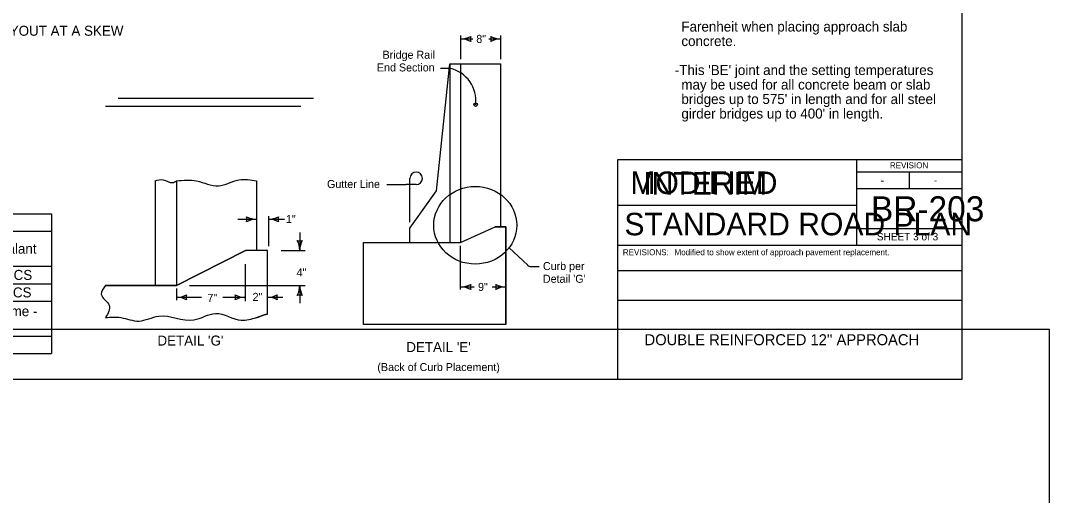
# Model space of a CAD drawing. Extents: x 10130 to 81668, y 5440 to 21644.
# Drawn here: x 18585 to 20643, y 7692 to 8642 of the extents above; entities that cross this region are included whole.
import ezdxf

# ---------------------------------------------------------------- set-up
doc = ezdxf.new("R2010")
doc.units = 0
for name, color, linetype in [('dsnCellElements', 7, 'Continuous'), ('dsnShtPlotShapeBatchPrint', 7, 'Continuous'), ('dsnstdblockInterim', 7, 'Continuous'), ('dsnStdBlockModified', 7, 'Continuous'), ('dsnStdBlockNotModified', 7, 'Continuous'), ('dsnStdBorder', 7, 'Continuous'), ('dsnStdLabel', 7, 'Continuous'), ('Level 1', 7, 'Continuous'), ('Level 5', 7, 'Continuous'), ('SheetBorder', 7, 'Continuous')]:
    doc.layers.add(name, color=color, linetype=linetype)

msp = doc.modelspace()

# ---------------------------------------------------------------- linework, layer by layer
at = {"layer": 'dsnCellElements'}
for p, q in [((19376.3, 8313.6), (19356.3, 8313.6)), ((19363.8, 8306.1), (19363.8, 8326.1))]:
    msp.add_line(p, q, dxfattribs=at)
msp.add_circle((19495.2, 8473.6), 3.54, dxfattribs=at)
msp.add_arc((19376.3, 8326.1), 12.5, 270, 180, dxfattribs=at)
at = {"layer": 'dsnShtPlotShapeBatchPrint'}
msp.add_lwpolyline([(17298.7, 5439.6), (20642.7, 5439.6), (20642.7, 8023.6), (17298.7, 8023.6)], close=True, dxfattribs=at)
at = {"layer": 'dsnStdBlockNotModified'}
for centre, radius, start, end in [((19465.1, 8647.4), 42.5, 270, 298.0725), ((19465.1, 8562.4), 42.5, 61.9275, 90), ((19500.8, 8604.9), 16.4, 162.2666, 197.7334), ((19509.8, 8604.9), 16.4, 342.2666, 17.7333), ((19545.4, 8647.4), 42.5, 241.9275, 270), ((19545.4, 8562.4), 42.5, 90, 118.0725), ((19021.3, 8244.2), 16.4, 342.2666, 17.7333), ((19056.9, 8286.7), 42.5, 241.9275, 270), ((19056.9, 8201.7), 42.5, 90, 118.0725), ((19080.7, 8286.7), 42.5, 270, 298.0725), ((19080.7, 8201.7), 42.5, 61.9275, 90), ((19116.4, 8244.2), 16.4, 162.2666, 197.7334), ((19143.4, 8217.5), 16.4, 252.2666, 287.7333), ((19100.9, 8181.9), 42.5, 360, 28.0725), ((19185.9, 8181.9), 42.5, 151.9275, 180), ((19100.9, 8112), 42.5, 331.9275, 360), ((19185.9, 8112), 42.5, 180, 208.0725), ((19465.1, 8151.4), 42.5, 270, 298.0725), ((19465.1, 8066.4), 42.5, 61.9275, 90), ((19500.8, 8108.9), 16.4, 162.2666, 197.7334), ((19519.7, 8108.9), 16.4, 342.2666, 17.7333), ((19555.4, 8151.4), 42.5, 241.9275, 270), ((19555.4, 8066.4), 42.5, 90, 118.0725), ((18896.9, 8130.6), 42.5, 270, 298.0725), ((18896.9, 8045.6), 42.5, 61.9275, 90), ((18932.5, 8088.1), 16.4, 162.2666, 197.7334), ((18998.4, 8088.1), 16.4, 342.2666, 17.7333), ((19034, 8130.6), 42.5, 241.9275, 270), ((19034, 8045.6), 42.5, 90, 118.0725), ((19143.4, 8076.3), 16.4, 72.2666, 107.7334)]:
    msp.add_arc(centre, radius, start, end, dxfattribs=at)
at = {"layer": 'dsnStdBorder'}
for p, q in [((19465.1, 8604.9), (19489.8, 8604.9)), ((19465.4, 8564.3), (19465.4, 8611.6)), ((19521.7, 8604.9), (19545.4, 8604.9)), ((19545.4, 8564.3), (19545.4, 8611.6)), ((19417.1, 8301.2), (19443.8, 8555.2)), ((19444.1, 8546), (19424.6, 8546)), ((19443.8, 8555.2), (19545.1, 8555.2)), ((19443.8, 8555.2), (19443.8, 8197.6)), ((19465.1, 8555.2), (19465.1, 8197.6)), ((19545.1, 8555.2), (19545.1, 8229.2)), ((18780.2, 8486.5), (19171.1, 8486.5)), ((18754.9, 8470.5), (19145.8, 8470.5)), ((19492.9, 8474.8), (19495.2, 8473.6)), ((18854.2, 8321), (18854.2, 8111.9)), ((18896.9, 8321), (18896.9, 8111.9)), ((19056.9, 8321), (19056.9, 8181.9)), ((19317.4, 8313.6), (19356.3, 8313.6)), ((19363.8, 8238.2), (19363.8, 8306.1)), ((19363.8, 8226.5), (19417.1, 8301.2)), ((18311.9, 8255.4), (18647, 8255.4)), ((18647, 8255.4), (18647, 7975.4)), ((19545.1, 8260.8), (19545.1, 8229.2)), ((19019.2, 8244.2), (19056.9, 8244.2)), ((19056.9, 8238.3), (19056.9, 8181.9)), ((19080.7, 8250.7), (19080.7, 8190.7)), ((19080.7, 8244.2), (19113, 8244.2)), ((18311.9, 8220.4), (18647, 8220.4)), ((19143.4, 8217.6), (19143.4, 8181.9)), ((19363.8, 8197.6), (19363.8, 8226.5)), ((19465.1, 8197.6), (19534.2, 8229.2)), ((19555.4, 8229.2), (19534.2, 8229.2)), ((19534.2, 8229.2), (19555.4, 8229.2)), ((19555.4, 8033.4), (19555.4, 8229.2)), ((19555.4, 8229.2), (19555.4, 8033.4)), ((19465.1, 8103.7), (19465.1, 8191.1)), ((19078.9, 8181.9), (19034.6, 8181.9)), ((19078.9, 8054.6), (19078.9, 8181.9)), ((19106.3, 8181.9), (19154.2, 8181.9)), ((19562.1, 8187.2), (19599.2, 8152.3)), ((18311.9, 8150.4), (18647, 8150.4)), ((19034, 8154.5), (19034, 8080.6)), ((19606, 8149.5), (19621.9, 8149.5)), ((18311.9, 8115.4), (18647, 8115.4)), ((18779.1, 8111.9), (18754.7, 8111.9)), ((18895.7, 8111.9), (18754.7, 8111.9)), ((18755, 8111.9), (18800.9, 8111.9)), ((18800.9, 8111.9), (18779.1, 8111.9)), ((18896.8, 8111.9), (18800.9, 8111.9)), ((18800.9, 8111.9), (18896.8, 8111.9)), ((18896.9, 8111.9), (18895.7, 8111.9)), ((18922.7, 8112), (19154.2, 8112)), ((19143.4, 8112), (19143.4, 8076.3)), ((19465.1, 8108.9), (19492.2, 8108.9)), ((19528, 8108.9), (19555.4, 8108.9)), ((18896.8, 8105.6), (18896.8, 8082.6)), ((18896.9, 8088.1), (18947.1, 8088.1)), ((18989.2, 8088.1), (19034, 8088.1)), ((19078.9, 8088.1), (19109.3, 8088.1)), ((18311.9, 8080.4), (18647, 8080.4)), ((18311.9, 8010.4), (18647, 8010.4)), ((18311.9, 7975.4), (18647, 7975.4))]:
    msp.add_line(p, q, dxfattribs=at)
for points in [[(19465.1, 8197.6), (19534.2, 8229.2)], [(19555.4, 8033.4), (19271, 8033.4), (19271, 8197.6), (19417.1, 8197.5), (19465.1, 8197.6)], [(19555.4, 8033.4), (19271, 8033.4), (19271, 8197.6), (19417.1, 8197.5), (19465.1, 8197.6)], [(19034.6, 8181.9), (18896.9, 8111.9), (18896.8, 8111.9)], [(18896.8, 8111.9), (19034.6, 8181.9)], [(19078.9, 8181.9), (19056.9, 8181.9), (19034.6, 8181.9)], [(19078.9, 8054.6), (19078.9, 8054.6), (19078.9, 8181.9)]]:
    msp.add_lwpolyline(points, dxfattribs=at)
for centre, radius, start, end in [((19429, 8481.1), 66.7, 353.5756, 76.8823), ((19606, 8159.5), 10, 226.7172, 270), ((19078.9, 8128.4), 40.3, 270, 298.0725), ((19078.9, 8047.8), 40.3, 61.9275, 90), ((19112.7, 8088.1), 15.6, 162.2666, 197.7334)]:
    msp.add_arc(centre, radius, start, end, dxfattribs=at)
msp.add_ellipse((19494.4, 8232.2), major_axis=(83, 0), ratio=0.93542, dxfattribs=at)
for points in [[(18854.2, 8321), (18869.9, 8323.4), (18889, 8317.6), (18896.9, 8321)], [(18896.9, 8321), (18937, 8321), (18980.7, 8310.9), (19021.5, 8323.2), (19056.9, 8321)], [(18754.7, 8111.9), (18746.4, 8094.3), (18762.2, 8072.1), (18755, 8047.6)], [(18754.7, 8111.9), (18746.4, 8094.3), (18762.2, 8072.1), (18755, 8047.6)], [(18755, 8047.6), (18785.5, 8047.6), (18821.7, 8040.6), (18861.3, 8050.5), (18931.3, 8042.9), (18975.1, 8055.8), (19026.4, 8042.4), (19056.9, 8047.6)], [(18755, 8047.6), (18785.5, 8047.6), (18821.7, 8040.6), (18861.3, 8050.5), (18931.3, 8042.9), (18975.1, 8055.8), (19026.4, 8042.4), (19056.9, 8047.6)], [(19056.9, 8047.6), (19071, 8052.7), (19076.3, 8054.2)]]:
    msp.add_spline(points, degree=3, dxfattribs=at)
msp.add_open_spline([(19056.9, 8047.6), (19057.8, 8047.9), (19058.7, 8048.2), (19059.6, 8048.5), (19060.6, 8048.8), (19061.5, 8049.2), (19062.4, 8049.5), (19064.2, 8050.2), (19066.1, 8051), (19067.9, 8051.7), (19069.7, 8052.3), (19071.5, 8053), (19073.4, 8053.5), (19074.3, 8053.8), (19075.2, 8054), (19076.1, 8054.2), (19076.6, 8054.3), (19077, 8054.4), (19077.5, 8054.4), (19077.9, 8054.5), (19078.4, 8054.5), (19078.9, 8054.6)], degree=3, dxfattribs=at)
at = {"layer": 'dsnStdLabel'}
for p, q in [((20256.6, 8364), (20256.6, 8272.7)), ((20256.6, 8339.1), (20467.5, 8339.1)), ((20362.1, 8339.1), (20362.1, 8305.9)), ((20256.6, 8305.9), (20467.5, 8305.9)), ((19779.5, 8272.7), (20256.6, 8272.7)), ((20256.6, 8272.7), (20256.6, 8192.7)), ((20467.5, 8224.9), (20256.6, 8224.9)), ((19779.5, 8192.7), (20467.5, 8192.7)), ((19779.5, 8141.7), (20467.5, 8141.7)), ((19779.5, 8082.7), (20467.5, 8082.7))]:
    msp.add_line(p, q, dxfattribs=at)
msp.add_lwpolyline([(19779.5, 8364), (20467.5, 8364), (20467.5, 7924), (19779.5, 7924)], close=True, dxfattribs=at)
msp.add_lwpolyline([(19779.5, 8364), (20467.5, 8364), (20467.5, 7924), (19779.5, 7924)], close=True, dxfattribs=at)
at = {"layer": 'SheetBorder'}
msp.add_lwpolyline([(17332.5, 9944), (20467.5, 9944), (20467.5, 7924), (17332.5, 7924)], close=True, dxfattribs=at)

# ---------------------------------------------------------------- texts
at = {"layer": 'dsnstdblockInterim'}
msp.add_text('INTERIM', height=45, dxfattribs=at).set_placement((19830.5, 8293.7))
at = {"layer": 'dsnStdBlockModified'}
for s, height, p in [('Approved List of Sealant', 20, (18325.5, 8175.4)), ('Dow - Dowsil 902 RCS', 20, (18336.3, 8122.9)), ('Sika - Sikasil 728 RCS', 20, (18337.8, 8087.9)), ('Watson Bowman Acme - ', 20, (18324.3, 8050.4)), ('(Back of Curb Placement)', 16, (19298.6, 7940.6))]:
    msp.add_text(s, height=height, dxfattribs=at).set_placement(p)
at = {"layer": 'dsnStdBlockNotModified'}
for s, height, p in [('APPROACH PAVEMENTS LAYOUT AT A SKEW', 20, (18200.7, 8611.3)), ('REVISIONS:', 12, (19789.5, 8172.3))]:
    msp.add_text(s, height=height, dxfattribs=at).set_placement(p)
at = {"layer": 'dsnStdBorder'}
for s, height, p in [('8"', 16, (19496.4, 8597.1)), ('Bridge Rail ', 16, (19309, 8565.3)), ('End Section', 16, (19297.7, 8539.9)), ('Gutter Line', 16, (19197.9, 8306.7)), ('1"', 16, (19115.7, 8236.7)), ('Curb per', 16, (19629.7, 8142.6)), ('4"', 16, (19137, 8129.8)), ("Detail 'G'", 16, (19629.7, 8117.2)), ('9"', 16, (19499.9, 8100.9)), ('7"', 16, (18958.7, 8078.9)), ('2"', 16, (19049, 8081)), ("DETAIL 'G'", 20, (18858.8, 7991.6)), ("DETAIL 'E'", 20, (19356.4, 7978.6))]:
    msp.add_text(s, height=height, dxfattribs=at).set_placement(p)
at = {"layer": 'dsnStdLabel'}
for s, height, p in [('REVISION', 12, (20323.6, 8346.2)), ('-', 15, (20305.1, 8314.7)), ('-', 15, (20411.6, 8315.1)), ('BR-203', 50, (20285.8, 8240.2)), ('STANDARD ROAD PLAN', 45.001, (19792.6, 8212.1)), ('SHEET 3 of 3', 15, (20297.6, 8202)), ('Modified to show extent of approach pavement replacement.', 12, (19892.8, 8172.3)), ("DOUBLE REINFORCED 12'' APPROACH", 22, (19833, 7992.3))]:
    msp.add_text(s, height=height, dxfattribs=at).set_placement(p)
at = {"layer": 'Level 1'}
for s, height, p in [('MODIFIED', 45, (19804.6, 8294.8)), ('REVISIONS:', 12, (19789.5, 8172.3))]:
    msp.add_text(s, height=height, dxfattribs=at).set_placement(p)
at = {"layer": 'Level 5'}
for s, p in [('Farenheit when placing approach slab ', (19906.6, 8619.7)), ('concrete.', (19906.6, 8590.7)), ("         -This 'BE' joint and the setting temperatures ", (19826.6, 8532.7)), ('may be used for all concrete beam or slab ', (19906.6, 8503.7)), ("bridges up to 575' in length and for all steel ", (19906.6, 8474.7)), ("girder bridges up to 400' in length.", (19906.6, 8445.7))]:
    msp.add_text(s, height=20, dxfattribs=at).set_placement(p)

doc.saveas('drawing.dxf')
